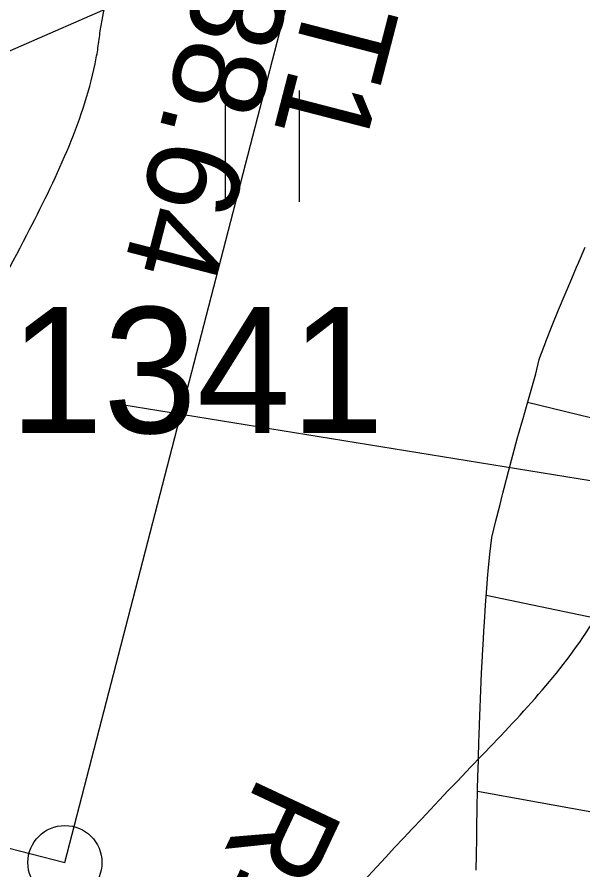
# Model space of a CAD drawing. Extents: x -564043 to -563833, y -1163561 to -1163412.
# Drawn here: x -563941.23 to -563933.6, y -1163487.91 to -1163476.4 of the extents above; entities that cross this region are included whole.
import ezdxf

# ---------------------------------------------------------------- set-up
doc = ezdxf.new("R2010")
doc.units = 0
for name, color, linetype in [('5', 7, 'Continuous'), ('_popis staničení PH1', 7, 'Continuous'), ('_popis staničení T1', 7, 'Continuous'), ('Line', 7, 'Continuous'), ('Parcelní čísla', 7, 'Continuous'), ('Vrstva 24', 7, 'Continuous'), ('Vrstva 26', 7, 'Continuous'), ('Značky kultur', 7, 'Continuous')]:
    doc.layers.add(name, color=color, linetype=linetype)

msp = doc.modelspace()

# ---------------------------------------------------------------- linework, layer by layer
msp.add_lwpolyline([(-563935.035, -1163487.916), (-563935.032, -1163487.702), (-563935.029, -1163487.488), (-563935.026, -1163487.273), (-563935.023, -1163487.14), (-563935.022, -1163487.059), (-563935.017, -1163486.845), (-563935.012, -1163486.631), (-563935.01, -1163486.566), (-563935.006, -1163486.406), (-563934.999, -1163486.176), (-563934.996, -1163486.096), (-563934.99, -1163485.947), (-563934.982, -1163485.717), (-563934.974, -1163485.486), (-563934.964, -1163485.256), (-563934.952, -1163485.026), (-563934.951, -1163485.009), (-563934.939, -1163484.796), (-563934.933, -1163484.682), (-563934.925, -1163484.567), (-563934.91, -1163484.337), (-563934.893, -1163484.107), (-563934.879, -1163483.923), (-563934.875, -1163483.878), (-563934.85, -1163483.65), (-563934.823, -1163483.422), (-563934.77, -1163483.199), (-563934.714, -1163482.978), (-563934.685, -1163482.861), (-563934.676, -1163482.825), (-563934.658, -1163482.756), (-563934.6, -1163482.535), (-563934.541, -1163482.314), (-563934.481, -1163482.094), (-563934.419, -1163481.874), (-563934.403, -1163481.818), (-563934.356, -1163481.654), (-563934.292, -1163481.435), (-563934.233, -1163481.214), (-563934.186, -1163481.019), (-563934.178, -1163480.992), (-563934.098, -1163480.782), (-563934.096, -1163480.778), (-563934.011, -1163480.564), (-563933.924, -1163480.351), (-563933.836, -1163480.138), (-563933.747, -1163479.926), (-563933.683, -1163479.776), (-563933.656, -1163479.715), (-563933.564, -1163479.504)])
at = {"layer": '5'}
for p, q in [((-563952.243, -1163481.627), (-563927.696, -1163470.887)), ((-563977.993, -1163478.142), (-563940.586, -1163487.812)), ((-563939.818, -1163481.63), (-563906.789, -1163486.973))]:
    msp.add_line(p, q, dxfattribs=at)
at = {"layer": '_popis staničení T1'}
msp.add_lwpolyline([(-563940.586, -1163487.812), (-563936.832, -1163473.29)], dxfattribs=at)
msp.add_circle((-563940.586, -1163487.812), 0.5, dxfattribs=at)
at = {"layer": 'Line'}
for p, q in [((-563929.542, -1163482.767), (-563934.342, -1163481.603)), ((-563930.091, -1163485.206), (-563934.9, -1163484.207)), ((-563930.561, -1163487.661), (-563935.017, -1163486.855))]:
    msp.add_line(p, q, dxfattribs=at)
at = {"layer": 'Vrstva 24'}
for points in [[(-563941.26, -1163493.011), (-563939.004, -1163490.701), (-563935.168, -1163486.585), (-563933.596, -1163484.774), (-563933.04, -1163483.789), (-563932.447, -1163481.939), (-563932.386, -1163481.578), (-563932.335, -1163479.091), (-563932.359, -1163478.881), (-563932.37, -1163478.699), (-563932.356, -1163477.982), (-563932.286, -1163477.265), (-563932.226, -1163476.548), (-563932.242, -1163475.831), (-563932.273, -1163475.745), (-563932.328, -1163475.651), (-563935.188, -1163471.035), (-563938.348, -1163465.934), (-563938.454, -1163465.786), (-563938.858, -1163465.285), (-563944.231, -1163458.582)], [(-563939.075, -1163507.623), (-563938.225, -1163507.164), (-563937.324, -1163506.641), (-563936.436, -1163506.097), (-563935.549, -1163505.552), (-563934.649, -1163505.03), (-563930.625, -1163502.906), (-563929.451, -1163502.347), (-563928.196, -1163501.635), (-563924.955, -1163499.225), (-563920.602, -1163495.57), (-563920.316, -1163495.267), (-563915.394, -1163488.268), (-563914.823, -1163487.183), (-563914.579, -1163485.87), (-563914.81, -1163484.102), (-563915.208, -1163482.646), (-563915.847, -1163480.252), (-563916.025, -1163479.9), (-563916.675, -1163479.113), (-563917.077, -1163478.648)]]:
    msp.add_spline(points, degree=3, dxfattribs=at)
at = {"layer": 'Vrstva 26'}
for points in [[(-563945.261, -1163485.579), (-563942.429, -1163481.606), (-563942.364, -1163481.506), (-563941.862, -1163480.718), (-563941.1, -1163479.337), (-563940.179, -1163477.031), (-563940.14, -1163476.815), (-563940.109, -1163476.584), (-563939.736, -1163474.248), (-563939.829, -1163473.919), (-563940.073, -1163473.538), (-563942.893, -1163468.839), (-563943.521, -1163467.678), (-563944.104, -1163466.494), (-563944.685, -1163465.307), (-563945.306, -1163464.14), (-563945.974, -1163463.136), (-563948.418, -1163460.207), (-563952.009, -1163455.848), (-563952.987, -1163454.388), (-563953.586, -1163453.328), (-563954.161, -1163452.255), (-563954.736, -1163451.183), (-563955.25, -1163450.271)], [(-563938.486, -1163500.528), (-563938.463, -1163500.513), (-563937.665, -1163500.022), (-563936.97, -1163499.566), (-563930.777, -1163494.949), (-563928.884, -1163493.45), (-563928.656, -1163493.192), (-563928.195, -1163492.447), (-563924.372, -1163485.735), (-563923.788, -1163484.5), (-563923.604, -1163483.639), (-563923.611, -1163481.604), (-563923.712, -1163481.017), (-563924.518, -1163478.475), (-563924.689, -1163477.919), (-563924.751, -1163477.798), (-563925.518, -1163476.583), (-563926.306, -1163475.384), (-563927.092, -1163474.184), (-563927.851, -1163472.968), (-563928.532, -1163471.813), (-563929.192, -1163470.645), (-563929.849, -1163469.476), (-563930.525, -1163468.317), (-563930.688, -1163468.07), (-563931.156, -1163467.471), (-563931.276, -1163467.321)]]:
    msp.add_spline(points, degree=3, dxfattribs=at)
at = {"layer": 'Značky kultur'}
for p, q in [((-563938.421, -1163478.89), (-563938.421, -1163477.39)), ((-563937.42, -1163478.89), (-563937.42, -1163477.39))]:
    msp.add_line(p, q, dxfattribs=at)

# ---------------------------------------------------------------- texts
at = {"layer": '_popis staničení PH1'}
msp.add_text('R=100m alfa=6.44%%d', height=1.25, rotation=244.8543, dxfattribs=at).set_placement((-563937.947, -1163486.606))
at = {"layer": '_popis staničení T1'}
for s, p in [('0+038.64', (-563938.042, -1163472.977)), ('KU T1 ', (-563936.59, -1163473.352))]:
    msp.add_text(s, height=1.25, rotation=255.5058, dxfattribs=at).set_placement(p)
at = {"layer": 'Parcelní čísla'}
msp.add_text('1341', height=1.7, dxfattribs=at).set_placement((-563941.334, -1163482.014))

doc.saveas('drawing.dxf')
